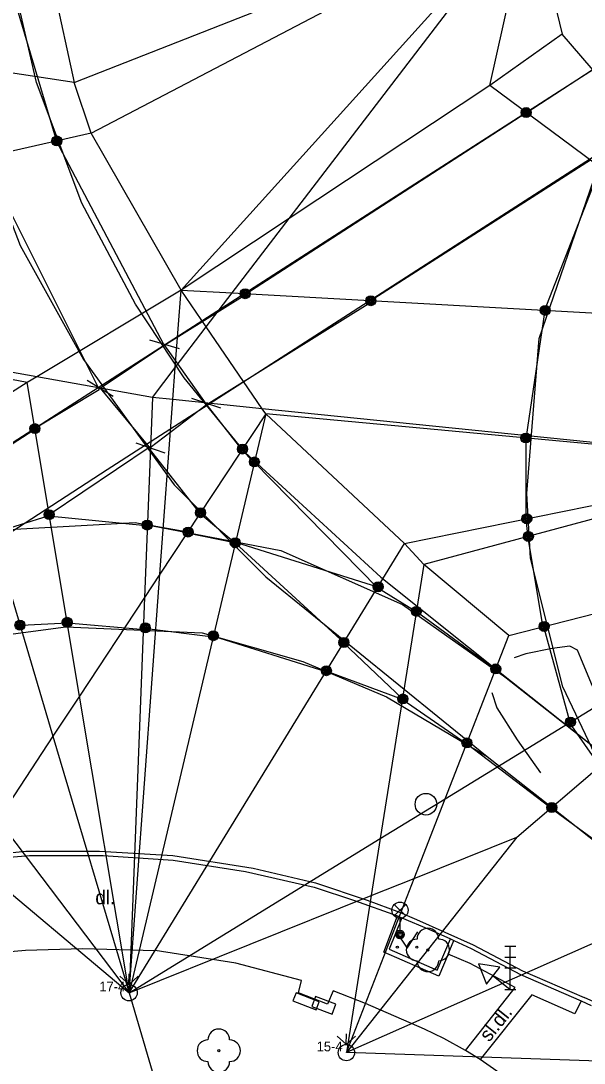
# Model space of a CAD drawing. Extents: x -598168 to -598014, y -1160410 to -1160294.
# Drawn here: x -598103.47 to -598077.42, y -1160366.48 to -1160318.27 of the extents above; entities that cross this region are included whole.
import ezdxf

# ---------------------------------------------------------------- set-up
doc = ezdxf.new("R2010")
doc.units = 0
for name, color, linetype in [('Kabelové vedení_Kabely', 7, 'Continuous'), ('Level 10', 7, 'Continuous'), ('Level 11', 7, 'Continuous'), ('Level 13', 7, 'Continuous'), ('Level 22', 7, 'Continuous'), ('Level 24', 7, 'Continuous'), ('Level 27', 7, 'Continuous'), ('Level 33', 7, 'Continuous'), ('Level 34', 7, 'Continuous'), ('Level 36', 7, 'Continuous'), ('Level 40', 7, 'Continuous'), ('Trolejové vedení_Nosné lano', 7, 'Continuous'), ('Trolejové vedení_Stožáry', 7, 'Continuous'), ('Trolejové vedení_Trolejový drát', 7, 'Continuous'), ('Trolejové vedení_Zavěšení', 7, 'Continuous')]:
    doc.layers.add(name, color=color, linetype=linetype)

# ---------------------------------------------------------------- blocks, each defined once
blk = doc.blocks.new('TRAKCN')
at = {"layer": 'Trolejové vedení_Stožáry'}
for points in [[(0, 0.0382), (-0.042, 0.0763)], [(-0.0008, 0.0382), (0.0004, 0.0868)], [(0, 0.0386), (0.0421, 0.0768)]]:
    blk.add_lwpolyline(points, dxfattribs=at)
blk.add_circle((0, 0), 0.0378, dxfattribs=at)
blk = doc.blocks.new('ZAVES1')
at = {"layer": 'Trolejové vedení_Zavěšení'}
for points in [[(0, 0), (-0.0035, 0.0035)], [(0, 0), (-0.0035, -0.0035)], [(0, 0), (0.0035, 0.0035)], [(0, 0), (0.0035, -0.0035)]]:
    blk.add_lwpolyline(points, dxfattribs=at)
for radius in [0.0231, 0.0194, 0.0147, 0.00975, 0.00529]:
    blk.add_circle((0, 0), radius, dxfattribs=at)
blk = doc.blocks.new('ZAVESE')
at = {"layer": 'Trolejové vedení_Zavěšení'}
blk.add_lwpolyline([(-0.0509, 0.0499), (0.0499, -0.0497)], dxfattribs=at)

msp = doc.modelspace()

# ---------------------------------------------------------------- linework, layer by layer
at = {"layer": 'Kabelové vedení_Kabely'}
for points in [[(-598064.76, -1160359.52), (-598066.02, -1160358.47), (-598067.41, -1160357.28), (-598068.67, -1160355.73), (-598070.01, -1160354.16), (-598070.4, -1160353.42), (-598070.76, -1160353.33), (-598071.29, -1160353.34), (-598072.33, -1160353.91), (-598072.7, -1160353.78), (-598073, -1160353.62), (-598074.56, -1160352.16), (-598076.07, -1160350.87), (-598076.6, -1160349.92), (-598077.09, -1160348.94), (-598077.58, -1160347.75), (-598077.73, -1160347.37), (-598078.08, -1160347.2), (-598078.91, -1160347.3), (-598080.12, -1160347.55), (-598080.666, -1160347.728)], [(-598081.693, -1160349.338), (-598081.46, -1160350.04), (-598080.52, -1160351.53), (-598079.442, -1160353.052)]]:
    msp.add_lwpolyline(points, dxfattribs=at)
at = {"layer": 'Level 10'}
for points in [[(-598109.14, -1160357.63), (-598106.05, -1160357.12), (-598103.08, -1160356.88), (-598099.66, -1160356.87), (-598096.43, -1160357.09), (-598093.08, -1160357.61), (-598089.91, -1160358.33)], [(-598089.91, -1160358.33), (-598088.05, -1160358.95), (-598086.06, -1160359.67)], [(-598086.06, -1160359.67), (-598085.85, -1160359.75)], [(-598085.85, -1160359.75), (-598084.61, -1160360.28), (-598083.61, -1160360.72)], [(-598083.61, -1160360.72), (-598083.45, -1160360.8)], [(-598083.45, -1160360.8), (-598082.65, -1160361.18)], [(-598082.65, -1160361.18), (-598080.37, -1160362.38), (-598077.57, -1160363.6)], [(-598077.57, -1160363.6), (-598077.1, -1160363.81)]]:
    msp.add_lwpolyline(points, dxfattribs=at)
at = {"layer": 'Level 11'}
for points in [[(-598109.18, -1160357.43), (-598106.06, -1160356.95), (-598103.24, -1160356.68), (-598099.83, -1160356.67), (-598096.45, -1160356.88), (-598092.73, -1160357.46), (-598089.85, -1160358.14)], [(-598089.85, -1160358.14), (-598087.46, -1160358.94), (-598085.97, -1160359.49), (-598085.18, -1160359.84), (-598082.56, -1160361)], [(-598083.71, -1160361.43), (-598084.15, -1160362.45), (-598086.69, -1160361.35), (-598086.06, -1160359.67)], [(-598085.85, -1160359.75), (-598086.44, -1160361.21), (-598084.22, -1160362.17), (-598083.61, -1160360.72)], [(-598083.71, -1160361.43), (-598083.45, -1160360.8)], [(-598082.56, -1160361), (-598080.28, -1160362.2), (-598077.43, -1160363.44)], [(-598108.67, -1160361.87), (-598106.07, -1160361.49), (-598103.25, -1160361.25), (-598100.62, -1160361.18), (-598097.26, -1160361.26)], [(-598090.63, -1160363.22), (-598090.49, -1160362.66), (-598093.53, -1160361.85), (-598097.26, -1160361.26)], [(-598082.91, -1160365.89), (-598080.61, -1160362.98), (-598082.69, -1160361.87), (-598083.71, -1160361.43)], [(-598089.3, -1160363.75), (-598090.63, -1160363.22)], [(-598082.91, -1160365.89), (-598083.91, -1160365.34), (-598084.8, -1160364.91), (-598087.54, -1160363.72), (-598089.03, -1160363.13), (-598089.3, -1160363.75)], [(-598077.57, -1160363.6), (-598077.85, -1160364.19), (-598079.84, -1160363.31), (-598082.24, -1160366.3)], [(-598071.32, -1160366.17), (-598077.43, -1160363.44)], [(-598082.24, -1160366.3), (-598082.91, -1160365.89)], [(-598074.84, -1160371.87), (-598077.41, -1160369.82), (-598080.58, -1160367.46), (-598082.24, -1160366.3)]]:
    msp.add_lwpolyline(points, dxfattribs=at)
at = {"layer": 'Level 13'}
for points in [[(-598086.82, -1160344), (-598093.1, -1160338.23), (-598095.92, -1160334.79), (-598098.17, -1160331.38), (-598100.65, -1160326.71), (-598102.75, -1160321.12), (-598104.11, -1160315.21), (-598104.64, -1160310.06), (-598104.953, -1160303.318)], [(-598108.27, -1160304.553), (-598107.87, -1160311.74), (-598106.05, -1160322.02), (-598103.5, -1160328.67), (-598100.58, -1160333.93), (-598096.39, -1160339.73), (-598092.15, -1160343.98)], [(-598064.29, -1160312.35), (-598084.82, -1160325.55), (-598094.41, -1160331.72), (-598107.12, -1160339.89), (-598119.33, -1160347.75)], [(-598067.38, -1160363.77), (-598072.6, -1160359.01), (-598075.73, -1160354.71), (-598078.41, -1160349.08), (-598079.9, -1160343.12), (-598080.08, -1160340.13), (-598079.5, -1160332.97), (-598076.99, -1160325.66), (-598074.25, -1160321.32), (-598069.66, -1160316.31), (-598064.29, -1160312.35)], [(-598119.48, -1160352.01), (-598099.48, -1160339.03), (-598083.17, -1160328.52), (-598067.68, -1160318.56), (-598060.92, -1160314.21)], [(-598119.33, -1160347.75), (-598111.85, -1160343.61), (-598105.99, -1160341.91), (-598098.18, -1160341.47), (-598091.45, -1160342.77), (-598085.82, -1160345.27), (-598080.78, -1160348.82)], [(-598092.15, -1160343.98), (-598083.94, -1160350.64), (-598081.91, -1160352.29)], [(-598086.82, -1160344), (-598080.78, -1160348.82)], [(-598119.48, -1160352.01), (-598113.32, -1160348.79), (-598107.77, -1160347.14), (-598101.39, -1160346.3), (-598095.09, -1160346.57), (-598090.43, -1160347.9), (-598086.57, -1160349.54), (-598081.91, -1160352.29)], [(-598080.78, -1160348.82), (-598062.76, -1160363.11)], [(-598081.91, -1160352.29), (-598079.04, -1160354.54), (-598067.38, -1160363.77)]]:
    msp.add_lwpolyline(points, dxfattribs=at)
at = {"layer": 'Level 22'}
for centre in [(-598084.65, -1160361.24), (-598094.32, -1160365.9)]:
    msp.add_circle(centre, 0.05, dxfattribs=at)
for centre, start, end in [((-598084.65, -1160360.74), 0, 180), ((-598085.15, -1160361.24), 90, 270), ((-598084.15, -1160361.24), 270, 90), ((-598084.65, -1160361.74), 180, 0), ((-598094.32, -1160365.4), 0, 180), ((-598094.82, -1160365.9), 90, 270), ((-598093.82, -1160365.9), 270, 90), ((-598094.32, -1160366.4), 180, 0)]:
    msp.add_arc(centre, 0.5, start, end, dxfattribs=at)
at = {"layer": 'Level 24'}
msp.add_lwpolyline([(-598089.68, -1160363.64), (-598090.74, -1160363.22), (-598090.89, -1160363.6), (-598089.82, -1160364.01), (-598089.68, -1160363.64)], dxfattribs=at)
msp.add_lwpolyline([(-598090.016, -1160363.859), (-598089.079, -1160364.209), (-598088.904, -1160363.741), (-598089.841, -1160363.391)], close=True, dxfattribs=at)
at = {"layer": 'Level 27'}
msp.add_circle((-598084.74, -1160354.5), 0.5, dxfattribs=at)
at = {"layer": 'Level 33'}
for p, q in [((-598086.205, -1160359.67), (-598085.675, -1160359.14)), ((-598086.205, -1160359.14), (-598085.675, -1160359.67)), ((-598085.94, -1160359.78), (-598085.94, -1160360.53)), ((-598081.09, -1160361.07), (-598080.59, -1160361.07)), ((-598080.84, -1160363.07), (-598080.84, -1160361.07)), ((-598081.09, -1160361.57), (-598080.59, -1160361.57)), ((-598081.09, -1160362.07), (-598080.59, -1160362.07)), ((-598081.09, -1160363.07), (-598080.59, -1160363.07))]:
    msp.add_line(p, q, dxfattribs=at)
for centre, radius in [((-598085.94, -1160359.405), 0.375), ((-598085.94, -1160360.53), 0.2), ((-598085.94, -1160360.53), 0.145), ((-598085.94, -1160360.53), 0.0876)]:
    msp.add_circle(centre, radius, dxfattribs=at)
at = {"layer": 'Level 34'}
msp.add_line((-598081.633, -1160362.431), (-598080.84, -1160363.07), dxfattribs=at)
msp.add_lwpolyline([(-598081.946, -1160362.82), (-598081.319, -1160362.042), (-598082.307, -1160361.888)], close=True, dxfattribs=at)
at = {"layer": 'Level 36'}
msp.add_lwpolyline([(-598086.11, -1160360.41), (-598085.61, -1160361.16), (-598085.11, -1160360.41)], dxfattribs=at)
for centre in [(-598086.06, -1160361.11), (-598085.161, -1160361.11)]:
    msp.add_circle(centre, 0.05, dxfattribs=at)
at = {"layer": 'Trolejové vedení_Nosné lano'}
for points in [[(-598101, -1160321.12), (-598079.91, -1160312.83)], [(-598101, -1160321.12), (-598079.91, -1160312.83)], [(-598100.22, -1160323.47), (-598079.91, -1160312.83)], [(-598100.22, -1160323.47), (-598079.91, -1160312.83)], [(-598096.06, -1160330.73), (-598079.91, -1160312.83)], [(-598096.06, -1160330.73), (-598079.91, -1160312.83)], [(-598091.07, -1160327.42), (-598079.91, -1160312.83)], [(-598091.07, -1160327.42), (-598079.91, -1160312.83)], [(-598081.79, -1160321.27), (-598079.91, -1160312.83)], [(-598081.79, -1160321.27), (-598079.91, -1160312.83)], [(-598079.91, -1160312.83), (-598078.44, -1160318.89)], [(-598079.91, -1160312.83), (-598078.44, -1160318.89)], [(-598101.94, -1160316.79), (-598101, -1160321.12)], [(-598101.94, -1160316.79), (-598101, -1160321.12)], [(-598078.44, -1160318.89), (-598081.79, -1160321.27)], [(-598078.44, -1160318.89), (-598081.79, -1160321.27)], [(-598066.85, -1160332.35), (-598078.44, -1160318.89)], [(-598066.85, -1160332.35), (-598078.44, -1160318.89)], [(-598101, -1160321.12), (-598112.8, -1160319.34)], [(-598101, -1160321.12), (-598112.8, -1160319.34)], [(-598100.22, -1160323.47), (-598101, -1160321.12)], [(-598100.22, -1160323.47), (-598101, -1160321.12)], [(-598081.79, -1160321.27), (-598091.07, -1160327.42)], [(-598081.79, -1160321.27), (-598091.07, -1160327.42)], [(-598066.85, -1160332.35), (-598081.79, -1160321.27)], [(-598066.85, -1160332.35), (-598081.79, -1160321.27)], [(-598100.22, -1160323.47), (-598129.09, -1160330.03)], [(-598100.22, -1160323.47), (-598129.09, -1160330.03)], [(-598096.06, -1160330.73), (-598100.22, -1160323.47)], [(-598096.06, -1160330.73), (-598100.22, -1160323.47)], [(-598091.07, -1160327.42), (-598096.06, -1160330.73)], [(-598091.07, -1160327.42), (-598096.06, -1160330.73)], [(-598093.7, -1160330.86), (-598091.07, -1160327.42)], [(-598093.7, -1160330.86), (-598091.07, -1160327.42)], [(-598102.74, -1160334.74), (-598129.09, -1160330.03)], [(-598103.18, -1160335), (-598129.09, -1160330.03)], [(-598102.74, -1160334.74), (-598129.09, -1160330.03)], [(-598103.18, -1160335), (-598129.09, -1160330.03)], [(-598096.06, -1160330.73), (-598102.74, -1160334.74)], [(-598096.06, -1160330.73), (-598102.74, -1160334.74)], [(-598096.33, -1160334.3), (-598096.06, -1160330.73)], [(-598096.33, -1160334.3), (-598096.06, -1160330.73)], [(-598096.06, -1160330.73), (-598093.7, -1160330.86)], [(-598094.9, -1160332.43), (-598096.06, -1160330.73)], [(-598096.06, -1160330.73), (-598093.7, -1160330.86)], [(-598094.9, -1160332.43), (-598096.06, -1160330.73)], [(-598094.9, -1160332.43), (-598093.7, -1160330.86)], [(-598094.9, -1160332.43), (-598093.7, -1160330.86)], [(-598093.7, -1160330.86), (-598066.85, -1160332.35)], [(-598093.7, -1160330.86), (-598066.85, -1160332.35)], [(-598096.33, -1160334.3), (-598094.9, -1160332.43)], [(-598096.33, -1160334.3), (-598094.9, -1160332.43)], [(-598092.32, -1160336.21), (-598094.9, -1160332.43)], [(-598092.32, -1160336.21), (-598094.9, -1160332.43)], [(-598097.39, -1160335.69), (-598096.33, -1160334.3)], [(-598097.39, -1160335.69), (-598096.33, -1160334.3)], [(-598096.44, -1160335.79), (-598096.33, -1160334.3)], [(-598096.44, -1160335.79), (-598096.33, -1160334.3)], [(-598102.74, -1160334.74), (-598103.18, -1160335)], [(-598102.74, -1160334.74), (-598103.18, -1160335)], [(-598097.39, -1160335.69), (-598102.74, -1160334.74)], [(-598097.39, -1160335.69), (-598102.74, -1160334.74)], [(-598103.18, -1160335), (-598106.26, -1160336.96)], [(-598103.18, -1160335), (-598106.26, -1160336.96)], [(-598100.76, -1160349.5), (-598103.18, -1160335)], [(-598100.76, -1160349.5), (-598103.18, -1160335)], [(-598097.39, -1160335.69), (-598097.75, -1160344.94)], [(-598097.39, -1160335.69), (-598097.75, -1160344.94)], [(-598096.44, -1160335.79), (-598097.39, -1160335.69)], [(-598096.44, -1160335.79), (-598097.39, -1160335.69)], [(-598097.04, -1160343.86), (-598096.44, -1160335.79)], [(-598097.04, -1160343.86), (-598096.44, -1160335.79)], [(-598092.32, -1160336.21), (-598096.44, -1160335.79)], [(-598092.32, -1160336.21), (-598096.44, -1160335.79)], [(-598067.47, -1160338.74), (-598092.32, -1160336.21)], [(-598092.15, -1160336.45), (-598092.32, -1160336.21)], [(-598067.47, -1160338.74), (-598092.32, -1160336.21)], [(-598092.15, -1160336.45), (-598092.32, -1160336.21)], [(-598092.15, -1160336.45), (-598098.47, -1160363.22)], [(-598092.15, -1160336.45), (-598098.47, -1160363.22)], [(-598092.15, -1160336.45), (-598097.04, -1160343.86)], [(-598092.15, -1160336.45), (-598097.04, -1160343.86)], [(-598067.47, -1160338.74), (-598092.15, -1160336.45)], [(-598085.73, -1160342.45), (-598092.15, -1160336.45)], [(-598067.47, -1160338.74), (-598092.15, -1160336.45)], [(-598085.73, -1160342.45), (-598092.15, -1160336.45)], [(-598106.26, -1160336.96), (-598101.99, -1160351.36)], [(-598106.26, -1160336.96), (-598101.99, -1160351.36)], [(-598085.73, -1160342.45), (-598067.47, -1160338.74)], [(-598085.73, -1160342.45), (-598067.47, -1160338.74)], [(-598067.47, -1160338.74), (-598084.84, -1160343.42)], [(-598067.47, -1160338.74), (-598084.84, -1160343.42)], [(-598098.47, -1160363.22), (-598085.73, -1160342.45)], [(-598098.47, -1160363.22), (-598085.73, -1160342.45)], [(-598084.84, -1160343.42), (-598085.73, -1160342.45)], [(-598084.84, -1160343.42), (-598085.73, -1160342.45)], [(-598083.85, -1160354.25), (-598064.82, -1160342.58)], [(-598083.85, -1160354.25), (-598064.82, -1160342.58)], [(-598080.91, -1160346.7), (-598064.82, -1160342.58)], [(-598080.91, -1160346.7), (-598064.82, -1160342.58)], [(-598080.53, -1160356.03), (-598064.82, -1160342.58)], [(-598080.53, -1160356.03), (-598064.82, -1160342.58)], [(-598084.84, -1160343.42), (-598086.85, -1160356.09)], [(-598084.84, -1160343.42), (-598086.85, -1160356.09)], [(-598080.91, -1160346.7), (-598084.84, -1160343.42)], [(-598080.91, -1160346.7), (-598084.84, -1160343.42)], [(-598098.47, -1160363.22), (-598097.04, -1160343.86)], [(-598098.47, -1160363.22), (-598097.04, -1160343.86)], [(-598097.04, -1160343.86), (-598097.75, -1160344.94)], [(-598097.04, -1160343.86), (-598097.75, -1160344.94)], [(-598097.75, -1160344.94), (-598100.76, -1160349.5)], [(-598097.75, -1160344.94), (-598100.76, -1160349.5)], [(-598097.75, -1160344.94), (-598098.47, -1160363.22)], [(-598097.75, -1160344.94), (-598098.47, -1160363.22)], [(-598083.85, -1160354.25), (-598080.91, -1160346.7)], [(-598083.85, -1160354.25), (-598080.91, -1160346.7)], [(-598100.76, -1160349.5), (-598101.99, -1160351.36)], [(-598100.76, -1160349.5), (-598101.99, -1160351.36)], [(-598098.47, -1160363.22), (-598100.76, -1160349.5)], [(-598098.47, -1160363.22), (-598100.76, -1160349.5)], [(-598101.99, -1160351.36), (-598104.54, -1160355.22)], [(-598101.99, -1160351.36), (-598104.54, -1160355.22)], [(-598101.99, -1160351.36), (-598098.47, -1160363.22)], [(-598101.99, -1160351.36), (-598098.47, -1160363.22)], [(-598086.85, -1160356.09), (-598083.85, -1160354.25)], [(-598086.85, -1160356.09), (-598083.85, -1160354.25)], [(-598085.28, -1160357.93), (-598083.85, -1160354.25)], [(-598085.28, -1160357.93), (-598083.85, -1160354.25)], [(-598104.54, -1160355.22), (-598098.47, -1160363.22)], [(-598104.54, -1160355.22), (-598098.47, -1160363.22)], [(-598098.47, -1160363.22), (-598086.85, -1160356.09)], [(-598098.47, -1160363.22), (-598086.85, -1160356.09)], [(-598080.53, -1160356.03), (-598088.42, -1160365.99)], [(-598080.53, -1160356.03), (-598088.42, -1160365.99)], [(-598086.85, -1160356.09), (-598087.27, -1160358.73)], [(-598086.85, -1160356.09), (-598087.27, -1160358.73)], [(-598085.28, -1160357.93), (-598080.53, -1160356.03)], [(-598085.28, -1160357.93), (-598080.53, -1160356.03)], [(-598105.77, -1160357.09), (-598098.47, -1160363.22)], [(-598105.77, -1160357.09), (-598098.47, -1160363.22)], [(-598088.42, -1160365.99), (-598085.28, -1160357.93)], [(-598088.42, -1160365.99), (-598085.28, -1160357.93)], [(-598087.27, -1160358.73), (-598085.28, -1160357.93)], [(-598087.27, -1160358.73), (-598085.28, -1160357.93)], [(-598098.47, -1160363.22), (-598087.27, -1160358.73)], [(-598098.47, -1160363.22), (-598087.27, -1160358.73)], [(-598087.27, -1160358.73), (-598088.42, -1160365.99)], [(-598087.27, -1160358.73), (-598088.42, -1160365.99)], [(-598072.87, -1160359.11), (-598088.42, -1160365.99)], [(-598072.87, -1160359.11), (-598088.42, -1160365.99)], [(-598098.47, -1160363.22), (-598093.46, -1160380.29)], [(-598098.47, -1160363.22), (-598093.46, -1160380.29)], [(-598067.34, -1160366.71), (-598088.42, -1160365.99)], [(-598067.34, -1160366.71), (-598088.42, -1160365.99)]]:
    msp.add_lwpolyline(points, dxfattribs=at)
at = {"layer": 'Trolejové vedení_Trolejový drát'}
for points in [[(-598103.78, -1160317.255), (-598101.831, -1160323.837)], [(-598080.146, -1160322.558), (-598077.055, -1160320.548)], [(-598093.111, -1160330.928), (-598080.124, -1160322.529)], [(-598096.861, -1160333.238), (-598101.831, -1160323.837)], [(-598105.191, -1160324.686), (-598099.852, -1160335.321)], [(-598087.312, -1160331.227), (-598077.125, -1160324.698)], [(-598079.255, -1160331.679), (-598076.691, -1160325.081)], [(-598096.855, -1160333.291), (-598093.096, -1160330.951)], [(-598094.909, -1160336.033), (-598087.293, -1160331.287)], [(-598080.105, -1160337.599), (-598079.233, -1160331.651)], [(-598099.806, -1160335.262), (-598096.855, -1160333.291)], [(-598096.861, -1160333.238), (-598094.916, -1160335.98)], [(-598102.877, -1160337.142), (-598099.852, -1160335.321)], [(-598099.806, -1160335.262), (-598097.481, -1160338.063)], [(-598097.487, -1160338.011), (-598094.909, -1160336.033)], [(-598094.916, -1160335.98), (-598093.26, -1160338.119)], [(-598105.684, -1160338.989), (-598102.87, -1160337.195)], [(-598080.099, -1160341.328), (-598080.108, -1160337.574)], [(-598102.164, -1160341.106), (-598097.494, -1160337.958)], [(-598097.533, -1160338.07), (-598095.181, -1160341.08)], [(-598093.25, -1160338.083), (-598092.73, -1160338.684)], [(-598092.686, -1160338.679), (-598086.976, -1160344.493)], [(-598104.776, -1160341.968), (-598102.21, -1160341.165)], [(-598102.21, -1160341.165), (-598097.674, -1160341.608)], [(-598095.189, -1160341.038), (-598093.547, -1160342.431)], [(-598097.655, -1160341.571), (-598095.746, -1160341.908)], [(-598080.019, -1160342.167), (-598080.099, -1160341.328)], [(-598095.784, -1160341.957), (-598093.596, -1160342.393)], [(-598079.313, -1160346.347), (-598080.019, -1160342.167)], [(-598093.552, -1160342.388), (-598086.982, -1160344.45)], [(-598093.547, -1160342.431), (-598088.522, -1160347.044)], [(-598087.009, -1160344.461), (-598085.194, -1160345.596)], [(-598085.198, -1160345.571), (-598081.514, -1160348.271)], [(-598103.44, -1160346.227), (-598101.32, -1160346.12)], [(-598101.32, -1160346.12), (-598097.762, -1160346.419)], [(-598097.769, -1160346.366), (-598094.572, -1160346.764)], [(-598078.068, -1160350.718), (-598079.294, -1160346.294)], [(-598094.569, -1160346.724), (-598089.373, -1160348.36)], [(-598088.564, -1160347.023), (-598085.818, -1160349.635)], [(-598089.377, -1160348.334), (-598085.843, -1160349.639)], [(-598081.543, -1160348.249), (-598076.259, -1160352.419)], [(-598085.843, -1160349.639), (-598082.856, -1160351.706)], [(-598078.119, -1160350.724), (-598076.705, -1160352.758)], [(-598082.885, -1160351.684), (-598078.932, -1160354.685)], [(-598078.957, -1160354.688), (-598072.867, -1160359.142)]]:
    msp.add_lwpolyline(points, dxfattribs=at)

# ---------------------------------------------------------------- block references
at = {"layer": 'Trolejové vedení_Stožáry', "xscale": 10, "yscale": 10}
for p in [(-598098.47, -1160363.22), (-598088.42, -1160365.99)]:
    msp.add_blockref('TRAKCN', p, dxfattribs=at)
at = {"layer": 'Trolejové vedení_Zavěšení', "xscale": 10, "yscale": 10}
for p in [(-598080.11, -1160322.516), (-598101.808, -1160323.831), (-598093.099, -1160330.894), (-598087.289, -1160331.216), (-598079.223, -1160331.664), (-598102.824, -1160337.132), (-598080.122, -1160337.566), (-598093.222, -1160338.075), (-598092.675, -1160338.674), (-598102.16, -1160341.111), (-598095.165, -1160341.02), (-598080.077, -1160341.301), (-598097.63, -1160341.59), (-598095.74, -1160341.915), (-598093.558, -1160342.412), (-598080.004, -1160342.117), (-598086.954, -1160344.445), (-598085.183, -1160345.582), (-598103.512, -1160346.222), (-598101.329, -1160346.088), (-598079.275, -1160346.281), (-598097.719, -1160346.345), (-598094.571, -1160346.707), (-598088.535, -1160347.024), (-598089.345, -1160348.328), (-598081.511, -1160348.244), (-598078.06, -1160350.701), (-598082.844, -1160351.666), (-598078.921, -1160354.653)]:
    msp.add_blockref('ZAVES1', p, dxfattribs=at)
at = {"layer": 'Trolejové vedení_Zavěšení', "xscale": 10}
for name, p, yscale, rotation in [('ZAVESE', (-598096.833, -1160333.231), 10, 28.28511473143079), ('ZAVESE', (-598099.801, -1160335.26), 9.999999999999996, 12.66471798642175), ('ZAVESE', (-598094.904, -1160335.943), 10.000000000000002, 26.644721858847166), ('ZAVESE', (-598097.481, -1160338.02), 10, 25.729066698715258), ('ZAVES1', (-598085.805, -1160349.634), 10, 62.36412502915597)]:
    msp.add_blockref(name, p, dxfattribs=dict(at, yscale=yscale, rotation=rotation))

# ---------------------------------------------------------------- texts
at = {"layer": 'Level 40'}
msp.add_text(' dl.', height=0.65, dxfattribs=at).set_placement((-598100.27, -1160359.13))
msp.add_text('sl.dl.', height=0.65, rotation=51.25, dxfattribs=at).set_placement((-598081.82, -1160365.53))
at = {"layer": 'Trolejové vedení_Stožáry'}
for s, p in [('17-4', (-598099.847, -1160363.16)), ('15-4', (-598089.797, -1160365.93))]:
    msp.add_text(s, height=0.45, dxfattribs=at).set_placement(p)

doc.saveas('drawing.dxf')
